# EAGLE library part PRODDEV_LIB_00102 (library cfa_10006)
CFAG12864B-TFH-V, 128x64 FSTN Positive, Transflective, Wide Temperature, White LED backlit LCD Module with Built-in Negative Voltage Generator
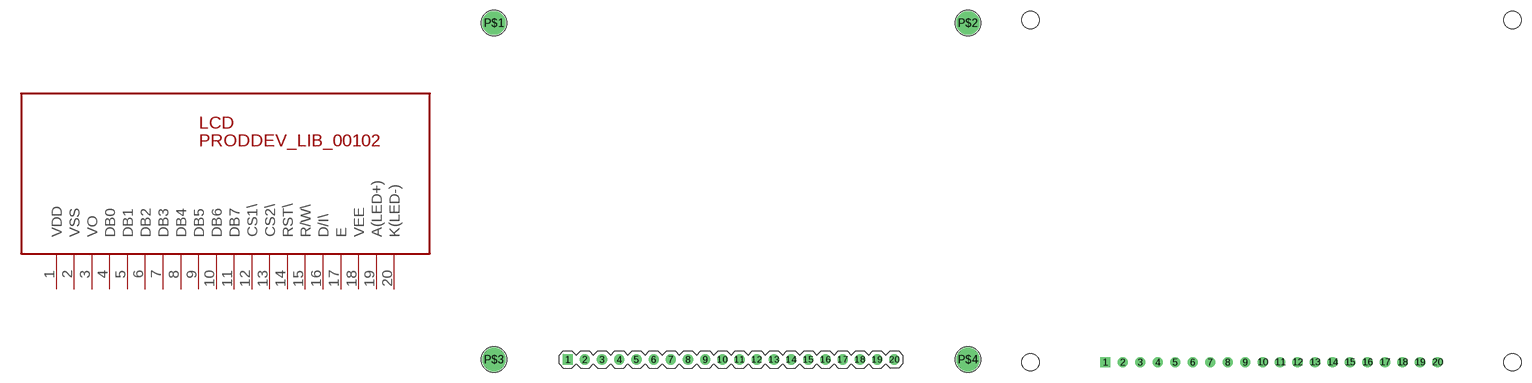
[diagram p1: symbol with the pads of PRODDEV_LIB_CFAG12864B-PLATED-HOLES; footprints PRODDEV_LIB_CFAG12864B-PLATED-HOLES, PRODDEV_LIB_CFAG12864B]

Designator prefix LCD

## PRODDEV_LIB_00102  [PRODDEV_LIB_CFAG12864B-PLATED-HOLES]
1  VDD  pwr
2  VSS  pwr
3  VO  pas
4  DB0
5  DB1
6  DB2
7  DB3
8  DB4
9  DB5
10  DB6
11  DB7
12  CS1\  in
13  CS2\  in
14  RST\  in
15  R/W\  in
16  D/I\  in
17  E  in
18  VEE  pas
19  A(LED+)  pas
20  K(LED-)  pas

## PRODDEV_LIB_00102NON-PLATED-HOLES  [PRODDEV_LIB_CFAG12864B]
Pads as for PRODDEV_LIB_CFAG12864B-PLATED-HOLES

## Footprint PRODDEV_LIB_CFAG12864B-PLATED-HOLES (pad centres in mm)
drill 1 square: 1 0,0
drill 1 round: 2 2.54,0; 3 5.08,0; 4 7.62,0; 5 10.16,0; 6 12.7,0; 7 15.24,0; 8 17.78,0; 9 20.32,0; 10 22.86,0; 11 25.4,0; 12 27.94,0; 13 30.48,0; 14 33.02,0; 15 35.56,0; 16 38.1,0; 17 40.64,0; 18 43.18,0; 19 45.72,0; 20 48.26,0
drill 2.5 round: P$1 -10.87,49.7; P$2 59.13,49.7; P$3 -10.87,0; P$4 59.13,0

## Footprint PRODDEV_LIB_CFAG12864B (pad centres in mm)
drill 1 square: 1 -0.016,-0.015
drill 1 round: 2 2.524,-0.015; 3 5.064,-0.015; 4 7.604,-0.015; 5 10.144,-0.015; 6 12.684,-0.015; 7 15.224,-0.015; 8 17.764,-0.015; 9 20.304,-0.015; 10 22.844,-0.015; 11 25.384,-0.015; 12 27.924,-0.015; 13 30.464,-0.015; 14 33.004,-0.015; 15 35.544,-0.015; 16 38.084,-0.015; 17 40.624,-0.015; 18 43.164,-0.015; 19 45.704,-0.015; 20 48.244,-0.015
hole 2.5 at -10.886,-0.015
hole 2.5 at 59.114,-0.015
hole 2.5 at -10.87,49.7
hole 2.5 at 59.13,49.7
